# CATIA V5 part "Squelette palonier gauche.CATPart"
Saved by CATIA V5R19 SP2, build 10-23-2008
Part number: Squelette palonier gauche
Bounding box of the stored display mesh (mm): x 599.222 to 630.035, y -118.911 to -102.57, z 50.325 to 75.191
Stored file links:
  D:\Mes Documents\ressource\CATIA\Ensemble Catia\Voiture_Telecommmande\SchemaCinematiqueFinal\Squelette palonier gauche.CATPart
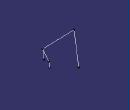
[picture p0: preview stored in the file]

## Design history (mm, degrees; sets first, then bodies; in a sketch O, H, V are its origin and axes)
AxisSystem1: origin (0, 0, 0), X (1, 0, 0), Y (0, 1, 0), Z (0, 0, 1)
Body1 (main body)
  Line1 to Line3: stored without definition
  Point1 to Point3: stored without definition
  Line4: stored without definition
  Line5: stored without definition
